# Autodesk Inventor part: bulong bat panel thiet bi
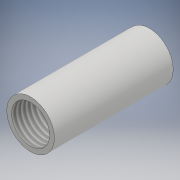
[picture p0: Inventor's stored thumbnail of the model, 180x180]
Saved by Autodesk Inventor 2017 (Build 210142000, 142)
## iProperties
Created: 2022-04
Part Number: bulong bat panel thiet bi
Material: Generic
Document SubType Name: Sheet Metal
Designer: phat
Density: 1 g/cm^3
Sheet Metal Rule: Default_mm
Appearance: Default
Author: phat
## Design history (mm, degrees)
sketch "Sketch1"
  geometry: C1 r 5 at (0, 0); 1 further point
  constraints: 1 centre point, 1 coincident
  dimensions: "d0" = 10 diameter of C1
extrude "Extrusion1" new body sketch "Sketch1" distance "d1" = 25; taper "d2" = 0 deg
sketch "Sketch2"
  geometry: C1 r 4 at (0, 0); 1 further point
  constraints: 1 centre point, 1 coincident
  dimensions: "d3" = 8 diameter of C1
hole "Hole1" sketch "Sketch2" at (0, 0) diameter "d4" = 8; stored, may be unused: countersink angle "d8" = 90 deg, drill point angle "d10" = 118 deg; dims "d5" = 6, "d6" = 4, "d7" = 2, "d9" = 0.5 (= Thickness)
thread "Thread1" dims "d11" = 10, "d12" = 0
body "Solid1"
other parameters: "Thickness" = 0.5, "BendRadius" = 0.5 (= Thickness), "BendReliefWidth" = 0.5 (= Thickness), "BendReliefDepth" = 0.25 (= 0.5 x Thickness), "CornerReliefSize" = 2 (= 4 x Thickness), "SeamGap" = 0.01, "MinimumRemnant" = 1 (= 2 x Thickness), "TransitionRadius" = 0.5 (= BendRadius), "JacobiRadiusSize" = 0.5 (= BendRadius), "GapSize" = 0.5 (= Thickness)
